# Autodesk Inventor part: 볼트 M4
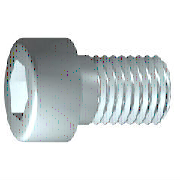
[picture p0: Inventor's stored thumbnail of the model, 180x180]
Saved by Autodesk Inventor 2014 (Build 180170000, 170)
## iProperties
IsCustomPart: 1
Created: 2012-02
Part Number: 볼트 M4
Material: 강철, 연강
Description: 6각머리 태핑 나사
Document SubType Name: Modeling
Standard: KS B 1003
Designer: mduedu
Standards Organization: KS
Language: ko-KR
Size Designation: M 4 x 10
Categories: <MemberInstance><Categories><Category DisplayName="조임쇠" InternalName="e4da775c-781d-43d5-af7c-5136215cf5a6" Mnemonic="FSTN"><Category DisplayName="볼트" InternalN
Density: 7.86 g/cm^3
Mass: 2.0371 g
Surface Area: 3.0572 cm^2
Volume: 0.259174 cm^3
Appearance: Steel
Author: mduedu
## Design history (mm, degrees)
sketch "스케치1"
  geometry: L1 (-1, 0)-(10, 0); L2 (10, 0)-(10, 2); L3 (10, 2)-(1.75, 2); L4 (1.75, 2)-(1.32, 2); L5 (1.32, 2)-(0, 2); L6 (0, 2)-(0, 3.5); L7 (0, 3.5)-(-4, 3.5); L8 (-4, 3.5)-(-4, 1.732); L9 (-4, 1.732)-(-2, 1.732); L10 (-2, 1.732)-(-1, 0); L11 (-6.8, 0)-(12.8, 0) reference; L12 (0, -0.7)-(0, 4.2) reference; L13 (1.75, 2)-(0, 2)
  constraints: 22 end point, 6 parallel, 2 collinear, 2 perpendicular, 1 horizontal, 1 point on line
  dimensions: "d1" = 8.25 distance from line of L3.end L2 (= GEL); "d2" = 0.42952 distance of L4.end L3.end (computed from GAL); "d3" = 4 distance between parallel lines of L8 L6 (= KOH); "d4" = 2 distance of L8.end L9.end (= INTI); "d5" = 60 deg angle of L10 L1; "d6" = 4 diameter of L3 L1 (= GD); "d7" = 4 diameter of L5 L1 (= BDM); "d8" = 3.4641 diameter of L9 L1 (= 1.1547 x SW); "d9" = 7 diameter of L7 L1 (= KOD); "d26" = 10 distance between parallel lines of L12 L2 (= NLG)
revolve "본체" sketch "스케치1" stored, may be unused: angle "d10" = 90 deg
sketch "스케치2"
  geometry: L1 (0, -4.9)-(0, 4.9) reference; L2 (-4.9, 0)-(4.9, 0) reference; L3 (1.732, 0)-(0.866, -1.5); L4 (0.866, -1.5)-(-0.866, -1.5); L5 (-0.866, -1.5)-(-1.732, 0); L6 (-1.732, 0)-(-0.866, 1.5); L7 (-0.866, 1.5)-(0.866, 1.5); L8 (0.866, 1.5)-(1.732, 0); 2 further points
  constraints: 12 end point, 1 coincident, 1 horizontal alignment, 1 point on line, 12 other
extrude "슬롯" join sketch "스케치2" stored distance "d11" = 10; taper "d12" = 0 deg
workplane "Work Plane1"
fillet "Fillet2" dims "d30" = 0.1 (= R)
body "Solid1"
fillet "모깎기1" dims "d17" = 0.4 (= RR)
feature "스레드" dims "d13" = 8.25 (= GEL), "d14" = 0
chamfer "모따기1" distance "d15" = 0.42941 (= -0.5 x SPD + 0.5 x GD); stored, may be unused: second distance "d16" = 0.42941 (= GUL), angle "d27" = 45 deg
other parameters: "GD" = 4 (= NND) [user parameter; used in 2 equation terms], "NLG" = 10 [user parameter; used in 1 equation term], "GEL" = 8.25 [user parameter; used in 2 equation terms], "KOD" = 7 [user parameter; used in 1 equation term], "KOH" = 4 [user parameter; used in 1 equation term], "INTI" = 2 [user parameter; used in 1 equation term], "GAL" = 0.42941 (= 0.61345 x PTC) [user parameter; used in 1 equation term], "GUL" = 0.42941 (= 0.61345 x PTC) [user parameter; used in 1 equation term], "BDM" = 4 (= NND) [user parameter; used in 1 equation term], "SW" = 3 [user parameter; used in 2 equation terms], "RR" = 0.4 [user parameter; used in 1 equation term], "SPD" = 3.14117 (= NND - 1.2269 x PTC) [user parameter; used in 1 equation term], "d19" = 0, "d28" = 0, "d29" = 0, "R" = 0.1 [user parameter; used in 1 equation term], "PHH" = 0.2 [user parameter], "GD1" = 3.14117 (= THREADDIA - 1.2269 x PTC) [user parameter], "THREADDIA" = 4 [user parameter; used in 1 equation term], "FAWI" = 45 deg [user parameter], "TPU" = 14.28571 (computed from PTC) [user parameter], "PTC" = 0.7 [user parameter; used in 5 equation terms], "NND" = 4 [user parameter; used in 3 equation terms], "TOA" = 30 deg [user parameter], "E0" = 3.465 (= 1.155 x SW) [user parameter]
